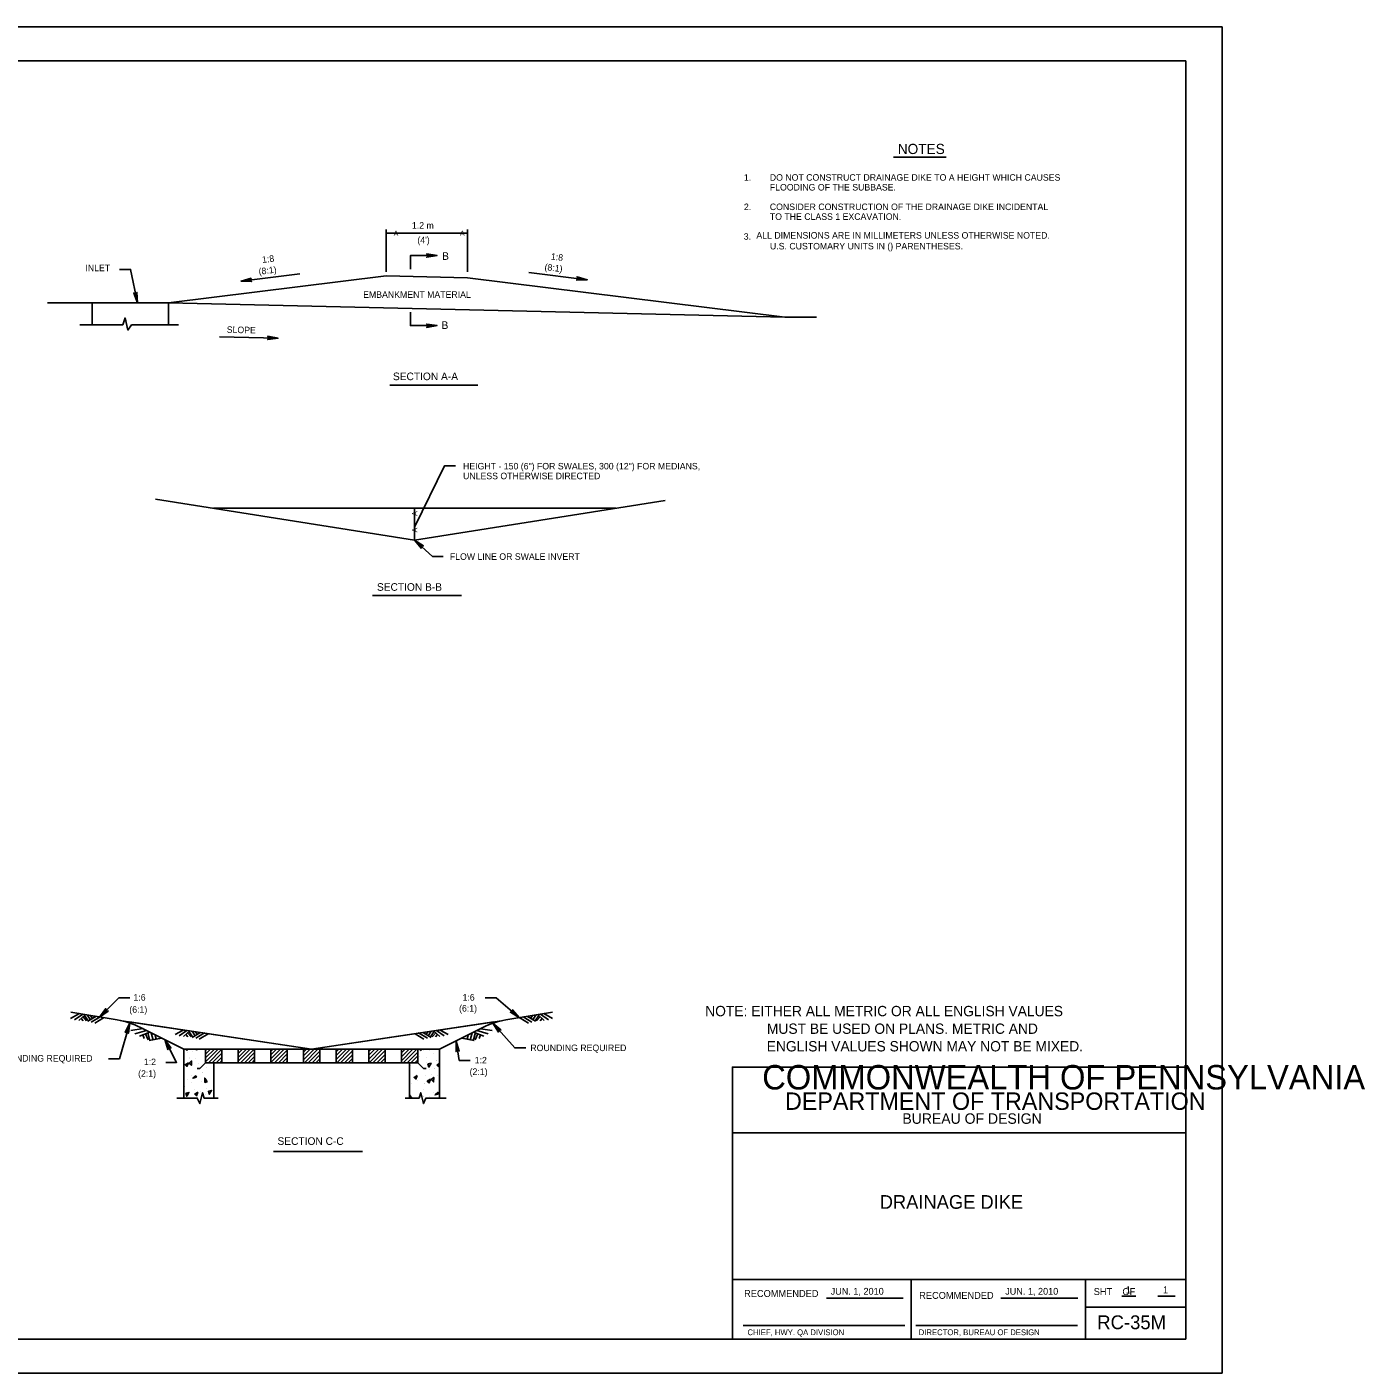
# Model space of a CAD drawing. Extents: x 69 to 973, y -48 to 546.
# Drawn here: x 382 to 973, y -48 to 546 of the extents above; entities that cross this region are included whole.
import ezdxf

# ---------------------------------------------------------------- set-up
doc = ezdxf.new("R2010")
doc.units = 0
for name, color, linetype in [('1', 7, 'Continuous'), ('2', 7, 'Continuous'), ('3', 7, 'Continuous'), ('40', 7, 'Continuous'), ('PLT-BNDY', 7, 'Continuous')]:
    doc.layers.add(name, color=color, linetype=linetype)

msp = doc.modelspace()

# ---------------------------------------------------------------- linework, layer by layer
at = {"layer": '1'}
for p, q in [((735.03, -15.05), (768.92, -15.05)), ((812.03, -15.05), (845.9, -15.05)), ((865.43, -14.07), (871.58, -14.07)), ((881.24, -14.07), (888.89, -14.07)), ((698.33, -27.05), (769.58, -27.05)), ((774.5, -27.05), (845.84, -27.05))]:
    msp.add_line(p, q, dxfattribs=at)
msp.add_lwpolyline([(893.57, -33.04), (893.57, 530.96), (107.57, 530.96), (107.57, -33.04), (893.57, -33.04), (893.57, -6.68), (693.57, -6.68), (693.57, 58), (893.57, 58), (893.57, 86.96), (693.57, 86.96), (693.57, -33.04), (772.37, -33.04), (772.37, -6.68), (772.37, -33.04), (849.37, -33.04), (849.37, -6.68), (849.37, -19), (893.57, -19)], dxfattribs=at)
at = {"layer": '2'}
for p, q in [((540.75, 437.83), (540.75, 456.63)), ((540.75, 454.95), (569.43, 454.95)), ((569.43, 454.95), (576.75, 454.95)), ((576.75, 437.83), (576.75, 456.63)), ((444.75, 424.15), (540.75, 436.15)), ((502.71, 437.03), (476.78, 433.79)), ((540.75, 436.15), (576.74, 435.31)), ((576.74, 435.31), (716.67, 417.82)), ((603.73, 437.61), (629.49, 434.39)), ((444.75, 424.15), (391.36, 424.15)), ((444.75, 424.15), (716.67, 417.82)), ((716.67, 417.82), (730.61, 417.82)), ((405.63, 414.55), (424.59, 414.55)), ((428.44, 414.55), (449.15, 414.55)), ((493.13, 408.6), (467.21, 409.21)), ((553.37, 319.54), (439, 337.6)), ((464.57, 333.56), (642.17, 333.56)), ((553.37, 319.54), (663.94, 337)), ((553.37, 319.54), (553.37, 333.56)), ((401.59, 108.45), (405.58, 110.62)), ((401.71, 111.22), (422.19, 107.81)), ((403.37, 107.84), (406.99, 110.39)), ((405.27, 107.52), (408.2, 110.14)), ((406.24, 108.38), (407.15, 107.36)), ((407.06, 109.12), (408.65, 107.33)), ((407.68, 109.8), (409.45, 107.19)), ((408.92, 110.02), (410.41, 107.82)), ((409.13, 107.18), (412.7, 109.33)), ((411.29, 108.48), (410.42, 109.77)), ((410.72, 106.79), (414.6, 109.11)), ((411.93, 109.44), (412.19, 109.02)), ((412.23, 106.41), (416.1, 108.74)), ((507.93, 94.92), (591.67, 107.41)), ((593.66, 107.81), (614.14, 111.22)), ((603.62, 106.41), (599.75, 108.74)), ((605.13, 106.79), (601.26, 109.11)), ((606.73, 107.18), (603.15, 109.33)), ((603.92, 109.44), (603.67, 109.02)), ((604.56, 108.48), (605.43, 109.77)), ((606.93, 110.02), (605.51, 107.92)), ((608.12, 109.72), (606.49, 107.32)), ((608.79, 109.12), (607.2, 107.33)), ((610.58, 107.52), (607.65, 110.14)), ((609.62, 108.38), (608.7, 107.36)), ((612.48, 107.84), (608.92, 110.35)), ((614.26, 108.45), (610.34, 110.58)), ((507.93, 94.92), (427.53, 106.92)), ((428.22, 103.08), (433.61, 103.95)), ((429.99, 101.69), (435.1, 103.13)), ((432.02, 100.57), (436.52, 102.42)), ((432.37, 104.49), (451.53, 94.92)), ((433.45, 101.16), (434.08, 99.64)), ((434.68, 101.66), (435.77, 99)), ((435.65, 102.19), (436.61, 98.53)), ((437.09, 102.13), (437.95, 98.85)), ((447.72, 101.38), (451.29, 103.32)), ((449.5, 100.78), (452.86, 103.13)), ((451.4, 100.45), (454.19, 102.94)), ((452.37, 101.32), (453.28, 100.29)), ((453.19, 102.05), (454.79, 100.26)), ((453.81, 102.73), (455.58, 100.12)), ((455.16, 102.79), (456.54, 100.75)), ((455.26, 100.11), (458.53, 102.08)), ((456.64, 102.57), (457.44, 101.38)), ((456.85, 99.72), (460.73, 102.04)), ((458.11, 102.29), (458.32, 101.95)), ((458.36, 99.34), (462.24, 101.67)), ((507.93, 94.92), (588.33, 106.92)), ((507.93, 94.92), (588.33, 106.92)), ((557.49, 99.34), (553.61, 101.67)), ((559, 99.72), (555.12, 102.04)), ((560.59, 100.11), (557.32, 102.08)), ((557.74, 102.29), (557.53, 101.95)), ((559.21, 102.57), (558.41, 101.38)), ((560.69, 102.79), (559.31, 100.75)), ((562.04, 102.73), (560.27, 100.12)), ((562.66, 102.05), (561.07, 100.26)), ((564.45, 100.45), (561.66, 102.94)), ((563.48, 101.32), (562.57, 100.29)), ((566.35, 100.78), (562.99, 103.13)), ((564.33, 94.92), (583.48, 104.49)), ((568.13, 101.38), (564.57, 103.32)), ((578.76, 102.13), (577.9, 98.85)), ((580.2, 102.19), (579.24, 98.53)), ((583.84, 100.57), (579.33, 102.42)), ((581.18, 101.66), (580.08, 99)), ((585.86, 101.69), (580.75, 103.13)), ((582.4, 101.16), (581.77, 99.64)), ((587.63, 103.08), (582.36, 103.93)), ((436.25, 98.65), (441.65, 99.76)), ((438.92, 100.87), (439.27, 99.48)), ((579.61, 98.65), (574.2, 99.76)), ((576.93, 100.87), (576.58, 99.48)), ((461.13, 88.92), (461.13, 94.92)), ((468.33, 88.92), (468.33, 94.92)), ((475.53, 88.92), (475.53, 94.92)), ((482.73, 88.92), (482.73, 94.92)), ((489.93, 88.92), (489.93, 94.92)), ((497.13, 88.92), (497.13, 94.92)), ((504.33, 88.92), (504.33, 94.92)), ((511.53, 88.92), (511.53, 94.92)), ((518.73, 88.92), (518.73, 94.92)), ((525.93, 88.92), (525.93, 94.92)), ((533.13, 88.92), (533.13, 94.92)), ((540.33, 88.92), (540.33, 94.92)), ((547.53, 88.92), (547.53, 94.92)), ((554.73, 88.92), (554.73, 94.92)), ((457.48, 73.32), (448.5, 73.32)), ((466.73, 73.32), (460.49, 73.32)), ((549.12, 73.32), (555.36, 73.32)), ((558.37, 73.32), (567.35, 73.32))]:
    msp.add_line(p, q, dxfattribs=at)
for points in [[(558.95, 445.63), (559.11, 445.31), (563.31, 445.08), (558.95, 445.63), (558.73, 445.82), (563.31, 445.08), (559.12, 444.87), (558.96, 444.56), (563.31, 445.08), (558.73, 444.35), (558.96, 444.56)], [(551.53, 439.08), (551.53, 445.08), (563.31, 445.08)], [(423.22, 438.95), (428.02, 438.95), (431.08, 424.21)], [(481.18, 433.78), (480.98, 434.08), (476.78, 433.79), (481.18, 433.78), (481.42, 433.62), (476.78, 433.79), (480.92, 434.51), (481.03, 434.84), (476.78, 433.79), (481.24, 435.08), (481.03, 434.84)], [(625.23, 435.47), (625.36, 435.14), (629.49, 434.39), (625.23, 435.47), (625.04, 435.69), (629.49, 434.39), (625.3, 434.7), (625.11, 434.41), (629.49, 434.39), (624.85, 434.23), (625.11, 434.41)], [(430.73, 428.59), (430.46, 428.36), (431.08, 424.21), (430.73, 428.59), (430.88, 428.84), (431.08, 424.21), (430.03, 428.27), (429.69, 428.36), (431.08, 424.21), (429.44, 428.55), (429.69, 428.36)], [(411.15, 414.55), (411.15, 424.15), (444.75, 424.15), (444.75, 414.55)], [(424.59, 414.55), (425.6, 417.58), (426.88, 412.21), (428.44, 414.55)], [(551.53, 420.14), (551.53, 414.14), (563.31, 414.14)], [(558.95, 413.59), (559.11, 413.91), (563.31, 414.14), (558.95, 413.59), (558.73, 413.4), (563.31, 414.14), (559.12, 414.35), (558.96, 414.66), (563.31, 414.14), (558.73, 414.87), (558.96, 414.66)], [(488.79, 409.25), (488.94, 408.93), (493.13, 408.6), (488.79, 409.25), (488.57, 409.45), (493.13, 408.6), (488.94, 408.5), (488.78, 408.19), (493.13, 408.6), (488.54, 407.98), (488.78, 408.19)], [(571.41, 352.35), (566.61, 352.35), (553.47, 325.57)], [(566, 312.3), (561.2, 312.3), (553.37, 319.54)], [(556.2, 316.18), (556.3, 316.52), (553.37, 319.54), (556.2, 316.18), (556.24, 315.89), (553.37, 319.54), (556.59, 316.85), (556.92, 316.97), (553.37, 319.54), (557.23, 316.96), (556.92, 316.97)], [(427.72, 117.51), (422.92, 117.51), (414.4, 109.01)], [(584.47, 117.51), (589.27, 117.51), (599.62, 108.78)], [(417.88, 111.71), (417.54, 111.81), (414.4, 109.01), (417.88, 111.71), (418.17, 111.73), (414.4, 109.01), (417.23, 112.12), (417.11, 112.45), (414.4, 109.01), (417.13, 112.77), (417.11, 112.45)], [(507.93, 94.92), (424.18, 107.42)], [(596.63, 112.01), (596.56, 111.67), (599.62, 108.78), (596.63, 112.01), (596.59, 112.3), (599.62, 108.78), (596.28, 111.33), (595.96, 111.19), (599.62, 108.78), (595.64, 111.18), (595.96, 111.19)], [(418.31, 90.65), (423.11, 90.65), (427.72, 106.49)], [(425.97, 102.46), (426.32, 102.52), (427.72, 106.49), (425.97, 102.46), (425.73, 102.3), (427.72, 106.49), (426.74, 102.41), (427, 102.17), (427.72, 106.49), (427.13, 101.89), (427, 102.17)], [(602.37, 95.47), (597.57, 95.47), (587.83, 106.32)], [(590.34, 102.71), (590.46, 103.04), (587.83, 106.32), (590.34, 102.71), (590.34, 102.42), (587.83, 106.32), (590.79, 103.34), (591.12, 103.44), (587.83, 106.32), (591.43, 103.4), (591.12, 103.44)], [(443.55, 89.05), (448.35, 89.05), (443.09, 99.15)], [(444.62, 95.03), (444.83, 95.32), (443.09, 99.15), (444.62, 95.03), (444.55, 94.74), (443.09, 99.15), (445.21, 95.52), (445.56, 95.53), (443.09, 99.15), (445.85, 95.42), (445.56, 95.53)], [(571.78, 94.07), (572.06, 94.28), (571.62, 98.46), (571.78, 94.07), (571.63, 93.81), (571.62, 98.46), (572.5, 94.35), (572.83, 94.25), (571.62, 98.46), (573.07, 94.05), (572.83, 94.25)], [(573.01, 89.93), (571.62, 98.46)], [(461.13, 94.92), (451.53, 94.92), (451.53, 73.32)], [(452.81, 94.3), (452.63, 94.92)], [(453.18, 94.92), (452.81, 94.3)], [(456.66, 94.92), (457.15, 94.48)], [(457.15, 94.48), (457.32, 94.92)], [(461.13, 89.33), (466.72, 94.92)], [(461.13, 91.02), (465.02, 94.92)], [(461.13, 92.72), (463.32, 94.92)], [(461.13, 94.42), (461.63, 94.92)], [(462.41, 88.92), (468.33, 94.83)], [(464.11, 88.92), (468.33, 93.13)], [(465.81, 88.92), (468.33, 91.43)], [(467.5, 88.92), (468.33, 89.74)], [(475.53, 89.57), (480.87, 94.92)], [(475.53, 91.26), (479.18, 94.92)], [(475.53, 92.96), (477.48, 94.92)], [(475.53, 94.66), (475.78, 94.92)], [(476.57, 88.92), (482.57, 94.92)], [(478.27, 88.92), (482.73, 93.37)], [(479.97, 88.92), (482.73, 91.68)], [(481.66, 88.92), (482.73, 89.98)], [(489.93, 88.99), (495.85, 94.92)], [(489.93, 90.69), (494.15, 94.92)], [(489.93, 92.39), (492.46, 94.92)], [(489.93, 94.08), (490.76, 94.92)], [(491.55, 88.92), (497.13, 94.49)], [(493.24, 88.92), (497.13, 92.8)], [(494.94, 88.92), (497.13, 91.1)], [(496.64, 88.92), (497.13, 89.4)], [(504.33, 90.23), (509.02, 94.92)], [(504.33, 91.92), (507.32, 94.92)], [(504.33, 93.62), (505.62, 94.92)], [(504.71, 88.92), (510.71, 94.92)], [(506.41, 88.92), (511.53, 94.03)], [(508.11, 88.92), (511.53, 92.33)], [(509.8, 88.92), (511.53, 90.64)], [(518.73, 90.36), (523.29, 94.92)], [(518.73, 92.05), (521.59, 94.92)], [(518.73, 93.75), (519.89, 94.92)], [(518.98, 88.92), (524.98, 94.92)], [(520.68, 88.92), (525.93, 94.16)], [(522.38, 88.92), (525.93, 92.46)], [(524.07, 88.92), (525.93, 90.77)], [(533.13, 90.49), (537.56, 94.92)], [(533.13, 92.18), (535.86, 94.92)], [(533.13, 93.88), (534.16, 94.92)], [(533.25, 88.92), (539.25, 94.92)], [(534.95, 88.92), (540.33, 94.29)], [(536.65, 88.92), (540.33, 92.6)], [(538.34, 88.92), (540.33, 90.9)], [(540.04, 88.92), (540.33, 89.2)], [(547.53, 89.81), (552.63, 94.92)], [(547.53, 91.51), (550.93, 94.92)], [(547.53, 93.21), (549.24, 94.92)], [(547.53, 94.9), (547.54, 94.92)], [(548.33, 88.92), (554.33, 94.92)], [(550.02, 88.92), (554.73, 93.62)], [(551.72, 88.92), (554.73, 91.92)], [(553.42, 88.92), (554.73, 90.22)], [(554.73, 94.92), (564.33, 94.92), (564.33, 73.32)], [(555.56, 94.92), (556.18, 94.36)], [(556.18, 94.36), (556.4, 94.92)], [(562.46, 94.92), (562.42, 94.88)], [(562.42, 94.88), (562.52, 94.92)], [(577.81, 89.93), (573.01, 89.93)], [(461.13, 88.92), (458.58, 86.37), (457.38, 86.37)], [(461.13, 88.92), (464.73, 88.92), (464.73, 73.32)], [(511.5, 88.92), (511.53, 88.94)], [(525.77, 88.92), (525.93, 89.07)], [(554.73, 88.92), (551.13, 88.92), (551.13, 73.32)], [(554.73, 88.92), (557.27, 86.37), (558.47, 86.37)], [(564.33, 88.62), (563.18, 87.9)], [(563.18, 87.9), (564, 87.17)], [(564, 87.17), (564.33, 88.03)], [(460.49, 73.32), (459.8, 75.64), (458.61, 70.88), (457.48, 73.32)], [(551.2, 73.32), (551.17, 74.8)], [(551.17, 74.8), (552.13, 73.32)], [(555.36, 73.32), (556.06, 75.64), (557.25, 70.88), (558.37, 73.32)]]:
    msp.add_lwpolyline(points, dxfattribs=at)
for points in [[(464.73, 73.32), (464.73, 88.92), (461.13, 88.92), (461.13, 94.92), (451.53, 94.92), (451.53, 73.32), (457.48, 73.32), (458.61, 70.88), (459.8, 75.64), (460.49, 73.32)], [(453.87, 88.76), (454.95, 89.7), (454.9, 87.76)], [(461.13, 88.92), (461.13, 94.92), (554.73, 94.92), (554.73, 88.92)], [(554.73, 88.92), (554.73, 94.92), (461.13, 94.92), (461.13, 88.92)], [(461.13, 88.92), (461.13, 94.92), (468.33, 94.92), (468.33, 88.92)], [(475.53, 88.92), (475.53, 94.92), (482.73, 94.92), (482.73, 88.92)], [(489.93, 88.92), (489.93, 94.92), (497.13, 94.92), (497.13, 88.92)], [(504.33, 88.92), (504.33, 94.92), (511.53, 94.92), (511.53, 88.92)], [(518.73, 88.92), (518.73, 94.92), (525.93, 94.92), (525.93, 88.92)], [(533.13, 88.92), (533.13, 94.92), (540.33, 94.92), (540.33, 88.92)], [(547.53, 88.92), (547.53, 94.92), (554.73, 94.92), (554.73, 88.92)], [(551.13, 73.32), (551.13, 88.92), (554.73, 88.92), (554.73, 94.92), (564.33, 94.92), (564.33, 73.32), (558.37, 73.32), (557.25, 70.88), (556.06, 75.64), (555.36, 73.32)], [(453.55, 88.92), (452.11, 88.02), (452.93, 87.29)], [(554.53, 83.3), (553.09, 82.4), (553.9, 81.67)], [(559.26, 88.38), (560.66, 88.66), (559.65, 86.99)], [(457.07, 82.52), (456.82, 83.1), (455.58, 82.03)], [(461.87, 80.44), (460.83, 80.2), (460.79, 82.1)], [(560.4, 81.61), (558.96, 80.71), (559.77, 79.98)], [(560.71, 81.46), (561.79, 82.39), (561.74, 80.45)], [(452.41, 75.53), (453.82, 75.8), (452.81, 74.14)], [(457.78, 75.95), (456.34, 75.05), (457.15, 74.32)], [(462.4, 76.42), (463.8, 76.69), (462.79, 75.02)], [(563.91, 75.22), (563.66, 75.79), (562.42, 74.72)]]:
    msp.add_lwpolyline(points, close=True, dxfattribs=at)
for centre, start, end in [((416.27, 72.3), 63.43518, 80.53742), ((599.58, 72.3), 99.46262, 116.56532)]:
    msp.add_arc(centre, 36, start, end, dxfattribs=at)
at = {"layer": '3'}
for p, q in [((764.59, 488.5), (787.93, 488.5)), ((542.39, 387.84), (581.21, 387.84)), ((534.8, 295.1), (574.11, 295.1)), ((491.06, 49.8), (530.31, 49.8))]:
    msp.add_line(p, q, dxfattribs=at)
at = {"layer": 'PLT-BNDY'}
msp.add_lwpolyline([(68.57, 545.96), (909.57, 545.96), (909.57, -48.04), (68.57, -48.04)], close=True, dxfattribs=at)

# ---------------------------------------------------------------- texts
at = {"layer": '1'}
for s, height, p in [('(6:1)', 2.88, (427.49, 110.95)), ('(6:1)', 2.88, (572.97, 111.47)), ('(2:1)', 2.88, (431.37, 82.74)), ('(2:1)', 2.88, (577.63, 83.51)), ('COMMONWEALTH OF PENNSYLVANIA', 10.7834, (706.72, 77.1)), ('DEPARTMENT OF TRANSPORTATION', 7.6843, (716.78, 68.11)), ('BUREAU OF DESIGN', 4.6221, (768.55, 61.95)), ('DRAINAGE DIKE', 6.04, (758.56, 24.45)), ('RECOMMENDED', 3.048, (698.73, -14.45)), ('JUN. 1, 2010', 3, (736.91, -13.45)), ('JUN. 1, 2010', 3, (813.91, -13.45)), ('SHT    OF', 3.048, (852.97, -13.61)), ('1', 3.12, (867.05, -12.86)), ('1', 3.12, (883.51, -12.86)), ('APPROVED', 0.0192, (736.59, -15.11)), ('RECOMMENDED', 3.048, (775.98, -15.28)), ('RC-35M', 6.096, (854.53, -28.67)), ('CHIEF, HWY. QA DIVISION', 2.54, (700.22, -31.31)), ('DIRECTOR, BUREAU OF DESIGN', 2.54, (775.76, -31.31))]:
    msp.add_text(s, height=height, dxfattribs=at).set_placement(p)
at = {"layer": '2'}
for s, height, p in [('A', 2.24, (544.11, 453.83)), ('A', 2.24, (573.39, 453.83)), ('   ALL DIMENSIONS ARE IN MILLIMETERS UNLESS OTHERWISE NOTED.', 2.88, (700.94, 452.55)), ('U.S. CUSTOMARY UNITS IN () PARENTHESES.', 2.88, (710.14, 447.78)), ('.', 1.12, (453.04, 93.16)), ('.', 1.12, (453.82, 90.9)), ('.', 1.12, (455.07, 93.65)), ('.', 1.12, (456.54, 90.64)), ('.', 1.12, (555.26, 91.44)), ('.', 1.12, (557.13, 94.16)), ('.', 1.12, (558.25, 88.96)), ('.', 1.12, (558.25, 88.96)), ('.', 1.12, (558.56, 91.09)), ('.', 1.12, (559.68, 94.09)), ('.', 1.12, (561.64, 93.06)), ('.', 1.12, (562.68, 89.88)), ('.', 1.12, (454.8, 83.18)), ('.', 1.12, (457.86, 88.38)), ('.', 1.12, (459.57, 84.58)), ('.', 1.12, (461.28, 86.82)), ('.', 1.12, (551.47, 87.59)), ('.', 1.12, (557.98, 83.05)), ('.', 1.12, (559.88, 85.85)), ('.', 1.12, (560.66, 83.59)), ('.', 1.12, (561.91, 86.34)), ('.', 1.12, (563.38, 83.33)), ('.', 1.12, (451.72, 78.24)), ('.', 1.12, (452.83, 81.24)), ('.', 1.12, (454.8, 80.21)), ('.', 1.12, (459.21, 80.41)), ('.', 1.12, (461.43, 77.65)), ('.', 1.12, (551.66, 79.51)), ('.', 1.12, (554.53, 81.07)), ('.', 1.12, (557.6, 79.72)), ('.', 1.12, (451.41, 76.1)), ('.', 1.12, (455.07, 73.49)), ('.', 1.12, (455.83, 77.03)), ('.', 1.12, (458.55, 76.3)), ('.', 1.12, (461.09, 74.74)), ('.', 1.12, (554.72, 73.73)), ('.', 1.12, (557.05, 76.84)), ('.', 1.12, (557.13, 74)), ('.', 1.12, (559.68, 73.93)), ('.', 1.12, (561.64, 75.88))]:
    msp.add_text(s, height=height, dxfattribs=at).set_placement(p)
for p in [(554.49, 330.2), (554.49, 322.9)]:
    msp.add_text('A', height=2.24, rotation=90, dxfattribs=at).set_placement(p)
at = {"layer": '3'}
for s, height, p in [('NOTES', 4.5, (766.53, 489.87)), ('1.  ', 2.88, (698.65, 478.1)), ('DO NOT CONSTRUCT DRAINAGE DIKE TO A HEIGHT WHICH CAUSES', 2.88, (710.08, 478.1)), ('FLOODING OF THE SUBBASE.', 2.88, (710.08, 473.78)), ('2.  ', 2.88, (698.65, 465.14)), ('TO THE CLASS 1 EXCAVATION.', 2.88, (710.08, 460.82)), ('CONSIDER CONSTRUCTION OF THE DRAINAGE DIKE INCIDENTAL', 2.88, (710.08, 465.14)), ('1.2 m', 2.88, (552.18, 456.95)), ("(4')", 2.88, (554.58, 450.48)), ('3.', 2.88, (698.57, 452.05)), ('B', 3.36, (565.49, 443.17)), ('INLET', 2.88, (408.12, 438.18)), ('EMBANKMENT MATERIAL', 2.88, (530.65, 426.42)), ('B', 3.36, (565.24, 412.7)), ('SECTION A-A', 3.36, (543.8, 390.09)), ('HEIGHT - 150 (6") FOR SWALES, 300 (12") FOR MEDIANS,', 2.88, (574.73, 350.7)), ('UNLESS OTHERWISE DIRECTED', 2.88, (574.73, 346.38)), ('.', 3.36, (553.02, 325.18)), ('FLOW LINE OR SWALE INVERT', 2.88, (568.91, 310.81)), ('SECTION B-B', 3.36, (536.75, 297.15)), ('1:6', 2.88, (429.32, 116.3)), ('1:6', 2.88, (574.51, 116.3)), ('ROUNDING REQUIRED', 2.88, (604.43, 94.03)), ('ROUNDING REQUIRED', 2.88, (368.91, 89.41)), ('1:2', 2.88, (433.91, 87.84)), ('1:2', 2.88, (579.87, 88.6)), ('SECTION C-C', 3.36, (492.87, 52.64))]:
    msp.add_text(s, height=height, dxfattribs=at).set_placement(p)
for s, rotation, p in [('1:8', 352.87422, (613.37, 443.33)), ('(8:1)', 7.12578, (484.74, 436.59)), ('1:8', 7.12578, (486.24, 441.79)), ('(8:1)', 352.87422, (610.58, 438.7)), ('SLOPE', 358.6671, (470.45, 410.98))]:
    msp.add_text(s, height=2.88, rotation=rotation, dxfattribs=at).set_placement(p)
at = {"layer": '40'}
for s, p in [('NOTE: EITHER ALL METRIC OR ALL ENGLISH VALUES', (681.56, 109.42)), ('MUST BE USED ON PLANS. METRIC AND', (708.78, 101.65)), ('ENGLISH VALUES SHOWN MAY NOT BE MIXED.', (708.71, 93.89))]:
    msp.add_text(s, height=4.5587, dxfattribs=at).set_placement(p)

doc.saveas('drawing.dxf')
